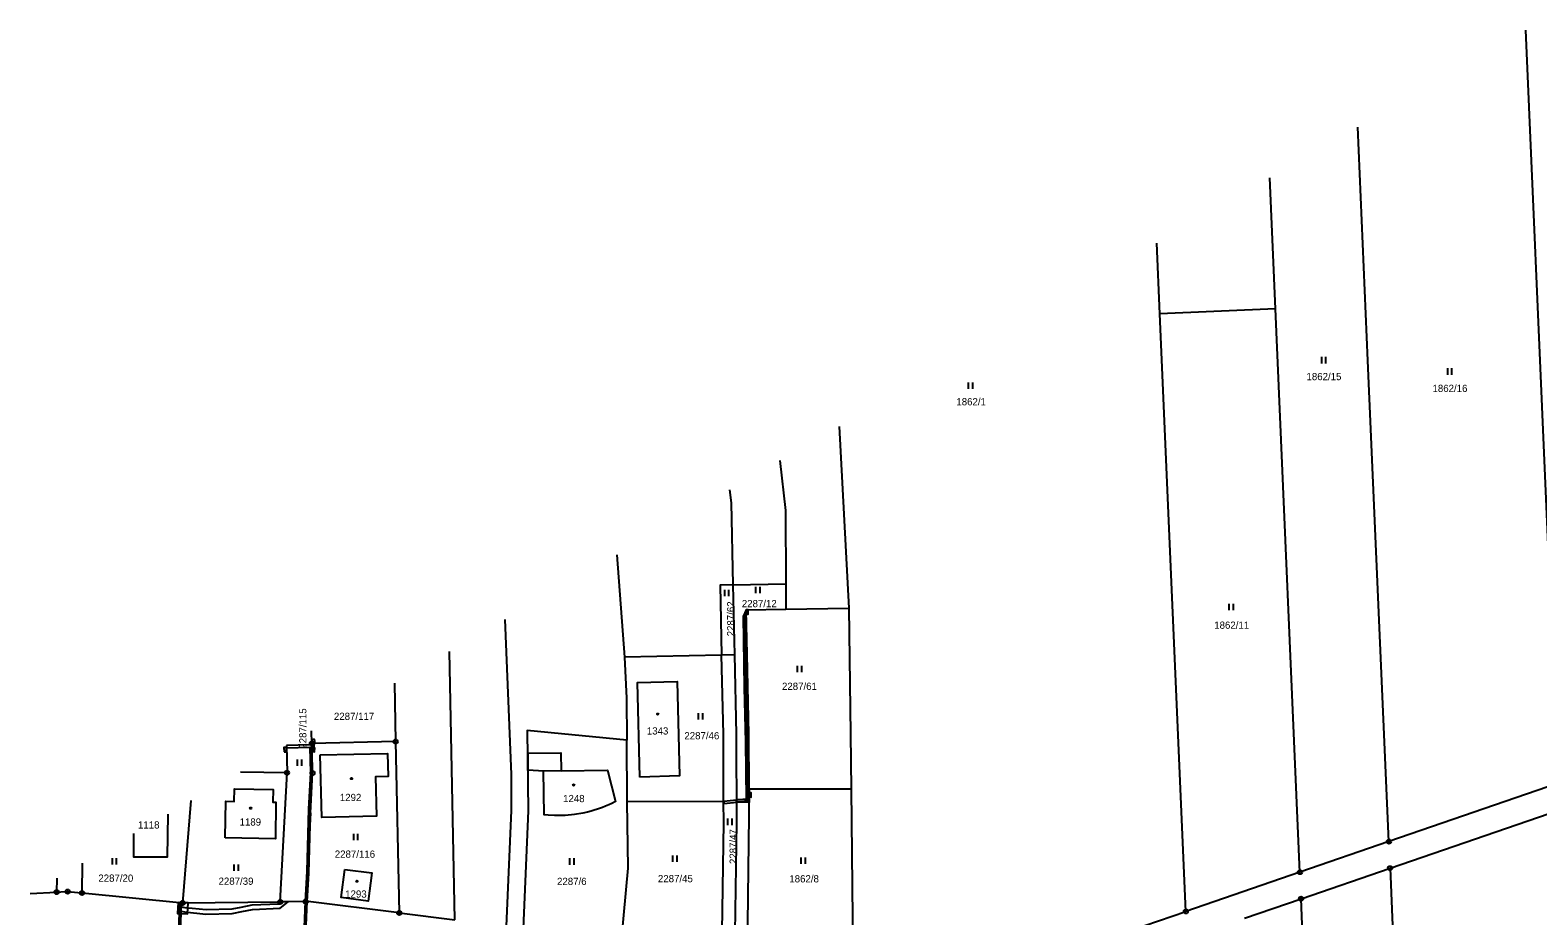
# Model space of a CAD drawing. Extents: x -758836 to -757729, y -1175316 to -1174366.
# Drawn here: x -758454.6 to -758099.9, y -1174637.3 to -1174428.8 of the extents above; entities that cross this region are included whole.
import ezdxf

# ---------------------------------------------------------------- set-up
doc = ezdxf.new("R2010")
doc.units = 0
for name, color, linetype in [('Hranice parcel', 7, 'Continuous'), ('Parcelní čísla', 7, 'Continuous'), ('Vnitřní kresba', 7, 'Continuous'), ('Věcná břemena k části', 7, 'Continuous'), ('Značky bodu BP', 7, 'Continuous'), ('Značky budov', 7, 'Continuous'), ('Značky kultur', 7, 'Continuous')]:
    doc.layers.add(name, color=color, linetype=linetype)

msp = doc.modelspace()

# ---------------------------------------------------------------- linework, layer by layer
at = {"layer": 'Hranice parcel'}
for p, q in [((-758094.97, -1174606.08), (-758102.68, -1174428.83)), ((-758161.61, -1174494.42), (-758162.95, -1174463.62)), ((-758188.8, -1174495.6), (-758189.52, -1174478.96)), ((-758161.61, -1174494.42), (-758188.8, -1174495.6)), ((-758182.68, -1174636.24), (-758188.8, -1174495.6)), ((-758155.84, -1174627.01), (-758161.61, -1174494.42)), ((-758289.28, -1174559.36), (-758276.79, -1174559.13)), ((-758289.28, -1174559.36), (-758288.91, -1174575.86)), ((-758276.79, -1174559.13), (-758276.77, -1174565.13)), ((-758276.77, -1174565.13), (-758261.99, -1174564.85)), ((-758354.67, -1174638.23), (-758355.96, -1174575.06)), ((-758291.91, -1174575.93), (-758314.73, -1174576.43)), ((-758288.91, -1174575.86), (-758291.91, -1174575.93)), ((-758368.92, -1174582.54), (-758368.63, -1174596.27)), ((-758388.32, -1174596.69), (-758388.38, -1174593.77)), ((-758394.31, -1174597.2), (-758394.18, -1174603.61)), ((-758368.63, -1174596.27), (-758388.32, -1174596.69)), ((-758368.63, -1174596.27), (-758367.77, -1174636.6)), ((-758314.16, -1174610.46), (-758314.25, -1174595.96)), ((-758394.18, -1174603.61), (-758405.13, -1174603.44)), ((-758395.77, -1174634), (-758394.18, -1174603.61)), ((-758094.97, -1174606.08), (-758134.89, -1174619.81)), ((-758285.46, -1174607.47), (-758285.9, -1174646.82)), ((-758261.42, -1174607.5), (-758285.46, -1174607.47)), ((-758261.42, -1174607.5), (-758261.03, -1174649.91)), ((-758291.45, -1174610.38), (-758314.16, -1174610.46)), ((-758134.62, -1174626.06), (-758094.69, -1174612.33)), ((-758134.89, -1174619.81), (-758155.84, -1174627.01)), ((-758155.84, -1174627.01), (-758182.68, -1174636.24)), ((-758155.57, -1174633.26), (-758134.62, -1174626.06)), ((-758134.62, -1174626.06), (-758130.45, -1174721.94)), ((-758454.62, -1174632.02), (-758448.39, -1174631.7)), ((-758442.4, -1174631.91), (-758418.72, -1174634.25)), ((-758418.72, -1174634.25), (-758395.77, -1174634)), ((-758389.77, -1174633.94), (-758395.77, -1174634)), ((-758168.89, -1174637.84), (-758155.57, -1174633.26)), ((-758152.07, -1174713.65), (-758155.57, -1174633.26)), ((-758367.77, -1174636.6), (-758354.67, -1174638.23))]:
    msp.add_line(p, q, dxfattribs=at)
for points in [[(-758134.89, -1174619.81), (-758139.82, -1174506.61), (-758142.21, -1174451.65)], [(-758264.27, -1174522.12), (-758261.99, -1174564.85)], [(-758278.19, -1174530.15), (-758276.85, -1174541.87), (-758276.79, -1174559.13)], [(-758290.03, -1174536.99), (-758289.7, -1174540.09), (-758289.28, -1174559.36)], [(-758316.58, -1174552.32), (-758314.73, -1174576.43)], [(-758289.28, -1174559.36), (-758292.28, -1174559.42), (-758291.91, -1174575.93)], [(-758285.46, -1174607.47), (-758285.5, -1174594.52), (-758285.91, -1174575.8), (-758286.14, -1174565.3), (-758276.77, -1174565.13)], [(-758261.99, -1174564.85), (-758261.59, -1174594.45), (-758261.42, -1174607.5)], [(-758342.95, -1174567.54), (-758341.45, -1174604.05), (-758341.43, -1174612.48), (-758342.58, -1174639.74)], [(-758314.73, -1174576.43), (-758314.27, -1174586.03), (-758314.25, -1174595.96)], [(-758291.45, -1174610.38), (-758291.5, -1174594.54), (-758291.91, -1174575.93)], [(-758288.91, -1174575.86), (-758288.5, -1174594.53), (-758288.43, -1174615.42), (-758288.89, -1174646.43)], [(-758311.15, -1174604.65), (-758311.72, -1174582.4), (-758302.38, -1174582.14), (-758301.8, -1174604.34), (-758311.15, -1174604.65)], [(-758314.25, -1174595.96), (-758337.67, -1174593.66), (-758337.43, -1174612.55), (-758338.6, -1174640.24)], [(-758389.77, -1174633.94), (-758388.18, -1174603.69), (-758388.32, -1174596.69)], [(-758386.35, -1174599.43), (-758370.51, -1174599.04), (-758370.38, -1174604.52), (-758373.34, -1174604.59), (-758373.1, -1174613.85), (-758386, -1174614.14), (-758386.35, -1174599.43)], [(-758332.74, -1174613.6), (-758333.68, -1174613.49), (-758333.82, -1174603.23), (-758337.4, -1174602.99), (-758337.47, -1174599), (-758329.76, -1174598.95), (-758329.68, -1174603.16), (-758318.75, -1174602.97), (-758316.89, -1174610.41), (-758317.73, -1174610.82), (-758318.48, -1174611.19), (-758319.21, -1174611.48), (-758319.98, -1174611.79), (-758321.1, -1174612.16), (-758321.88, -1174612.42), (-758322.64, -1174612.64), (-758323.44, -1174612.86), (-758324.57, -1174613.1), (-758326.53, -1174613.43), (-758328.71, -1174613.64), (-758330.15, -1174613.69), (-758331.27, -1174613.67), (-758332.74, -1174613.6)], [(-758408.71, -1174618.95), (-758408.59, -1174610.32), (-758406.58, -1174610.34), (-758406.55, -1174607.42), (-758397.43, -1174607.55), (-758397.52, -1174610.51), (-758396.8, -1174610.52), (-758396.9, -1174619.14), (-758408.71, -1174618.95)], [(-758418.72, -1174634.25), (-758416.76, -1174610.16)], [(-758315.47, -1174643.12), (-758313.89, -1174626.1), (-758314.16, -1174610.46)], [(-758291.89, -1174646.05), (-758291.43, -1174615.38), (-758291.45, -1174610.38)], [(-758422.24, -1174613.32), (-758422.37, -1174623.5), (-758430.22, -1174623.48), (-758430.2, -1174617.92)], [(-758442.4, -1174631.91), (-758442.32, -1174624.91)], [(-758380.61, -1174626.36), (-758374.22, -1174627.16), (-758375.09, -1174633.8), (-758381.45, -1174632.98), (-758380.61, -1174626.36)], [(-758448.35, -1174628.4), (-758448.39, -1174631.7)], [(-758448.39, -1174631.7), (-758447.39, -1174631.65), (-758445.79, -1174631.57), (-758443.39, -1174631.81), (-758442.4, -1174631.91)], [(-758367.77, -1174636.6), (-758389.23, -1174633.93), (-758389.77, -1174633.94)], [(-758212.86, -1174648.07), (-758198.75, -1174641.76), (-758182.68, -1174636.24)]]:
    msp.add_lwpolyline(points, dxfattribs=at)
at = {"layer": 'Vnitřní kresba'}
msp.add_line((-758329.68, -1174603.16), (-758333.82, -1174603.23), dxfattribs=at)
at = {"layer": 'Věcná břemena k části'}
for points in [[(-758286.12, -1174566.3), (-758286.14, -1174565.3), (-758286.82, -1174566.82), (-758286.63, -1174583.55), (-758286.32, -1174596.43), (-758286.12, -1174609.85), (-758288.45, -1174610.07), (-758288.45, -1174610.57), (-758285.62, -1174610.31), (-758285.82, -1174596.43), (-758286.13, -1174583.55), (-758286.32, -1174566.9)], [(-758285.69, -1174565.29), (-758286.14, -1174565.3), (-758286.12, -1174566.3), (-758285.67, -1174566.29)], [(-758394.85, -1174598.69), (-758394.28, -1174598.65), (-758394.31, -1174597.65), (-758394.91, -1174597.69)], [(-758394.31, -1174597.23), (-758394.3, -1174597.73), (-758388.8, -1174597.57), (-758388.68, -1174603.66), (-758389.13, -1174612.21), (-758389.5, -1174626.75), (-758389.93, -1174633.94), (-758389.77, -1174633.94), (-758388.67, -1174613.08), (-758388.18, -1174603.69), (-758388.28, -1174598.52), (-758388.31, -1174597.22), (-758388.8, -1174597.07)], [(-758387.69, -1174595.74), (-758388.34, -1174595.84), (-758388.32, -1174596.69), (-758387.55, -1174596.67)], [(-758387.54, -1174596.73), (-758387.55, -1174596.67), (-758388.32, -1174596.69), (-758388.32, -1174596.85)], [(-758388.31, -1174597.22), (-758388.28, -1174598.52), (-758388.1, -1174598.02), (-758387.8, -1174598.01), (-758387.82, -1174597.01), (-758388.31, -1174597.02)], [(-758387.65, -1174597.68), (-758388.3, -1174597.62), (-758388.28, -1174598.62), (-758387.74, -1174598.67)], [(-758285.97, -1174608.62), (-758285.95, -1174609.96), (-758288.45, -1174609.95), (-758288.45, -1174610.45), (-758285.49, -1174610.46), (-758285.48, -1174609.31), (-758285.47, -1174608.56)], [(-758285.47, -1174608.56), (-758285.48, -1174609.31), (-758284.98, -1174609.32), (-758284.97, -1174608.32), (-758285.47, -1174608.31)], [(-758388.67, -1174613.08), (-758389.77, -1174633.94), (-758389.42, -1174633.93), (-758389.03, -1174627.26)], [(-758288.45, -1174610.57), (-758288.45, -1174610.07), (-758291.36, -1174610.34), (-758291.32, -1174610.84)], [(-758417.46, -1174634.24), (-758418.72, -1174634.25), (-758419.79, -1174634.14), (-758419.91, -1174636.72), (-758417.57, -1174636.83)], [(-758419.22, -1174635.16), (-758419.42, -1174636.14), (-758418.28, -1174636.37), (-758413.27, -1174636.9), (-758407.06, -1174636.73), (-758404.82, -1174636.27), (-758402.33, -1174635.79), (-758395.76, -1174635.48), (-758393.88, -1174633.98), (-758395.51, -1174634), (-758396.14, -1174634.5), (-758402.45, -1174634.79), (-758405.02, -1174635.29), (-758407.18, -1174635.73), (-758413.23, -1174635.9), (-758418.12, -1174635.39)], [(-758389.42, -1174633.93), (-758389.77, -1174633.94), (-758389.93, -1174633.94), (-758390.26, -1174641.96), (-758389.02, -1174641.93), (-758387.42, -1174642.14), (-758387.35, -1174641.64), (-758388.96, -1174641.43), (-758389.74, -1174641.45)]]:
    msp.add_lwpolyline(points, close=True, dxfattribs=at)
msp.add_lwpolyline([(-758419.21, -1174641.86), (-758419.09, -1174636.24), (-758419.03, -1174634.95), (-758419.07, -1174634.22), (-758419.56, -1174634.17), (-758419.53, -1174634.93), (-758419.59, -1174636.22), (-758419.71, -1174641.86)], dxfattribs=at)
at = {"layer": 'Značky bodu BP'}
for centre, radius in [((-758388.32, -1174596.69), 0.5), ((-758388.32, -1174596.69), 0.0303), ((-758368.63, -1174596.27), 0.5), ((-758368.63, -1174596.27), 0.0303), ((-758394.18, -1174603.61), 0.5), ((-758394.18, -1174603.61), 0.0303), ((-758388.18, -1174603.69), 0.5), ((-758388.18, -1174603.69), 0.0303), ((-758134.89, -1174619.81), 0.5), ((-758134.89, -1174619.81), 0.0303), ((-758155.84, -1174627.01), 0.5), ((-758155.84, -1174627.01), 0.0303), ((-758134.62, -1174626.06), 0.5), ((-758134.62, -1174626.06), 0.0303), ((-758448.39, -1174631.7), 0.5), ((-758448.39, -1174631.7), 0.0303), ((-758445.79, -1174631.57), 0.5), ((-758445.79, -1174631.57), 0.0303), ((-758442.4, -1174631.91), 0.5), ((-758442.4, -1174631.91), 0.0303), ((-758418.72, -1174634.25), 0.5), ((-758418.72, -1174634.25), 0.0303), ((-758395.77, -1174634), 0.5), ((-758395.77, -1174634), 0.0303), ((-758389.77, -1174633.94), 0.5), ((-758389.77, -1174633.94), 0.0303), ((-758155.57, -1174633.26), 0.5), ((-758155.57, -1174633.26), 0.0303), ((-758367.77, -1174636.6), 0.5), ((-758367.77, -1174636.6), 0.0303), ((-758182.68, -1174636.24), 0.5), ((-758182.68, -1174636.24), 0.0303)]:
    msp.add_circle(centre, radius, dxfattribs=at)
at = {"layer": 'Značky budov'}
for centre in [(-758306.93, -1174589.81), (-758379, -1174604.98), (-758326.72, -1174606.5), (-758402.73, -1174611.95), (-758377.74, -1174629.14)]:
    msp.add_circle(centre, 0.175, dxfattribs=at)
at = {"layer": 'Značky kultur'}
for p, q in [((-758150.72, -1174507.25), (-758150.72, -1174505.75)), ((-758149.72, -1174507.25), (-758149.72, -1174505.75)), ((-758121.07, -1174509.92), (-758121.07, -1174508.42)), ((-758120.07, -1174509.92), (-758120.07, -1174508.42)), ((-758233.84, -1174513.25), (-758233.84, -1174511.75)), ((-758232.84, -1174513.25), (-758232.84, -1174511.75)), ((-758283.85, -1174561.38), (-758283.85, -1174559.88)), ((-758282.85, -1174561.38), (-758282.85, -1174559.88)), ((-758291.19, -1174562.04), (-758291.19, -1174560.54)), ((-758290.19, -1174562.04), (-758290.19, -1174560.54)), ((-758172.45, -1174565.38), (-758172.45, -1174563.88)), ((-758171.45, -1174565.38), (-758171.45, -1174563.88)), ((-758274.04, -1174579.94), (-758274.04, -1174578.44)), ((-758273.04, -1174579.94), (-758273.04, -1174578.44)), ((-758297.35, -1174591.1), (-758297.35, -1174589.6)), ((-758296.35, -1174591.1), (-758296.35, -1174589.6)), ((-758391.71, -1174601.98), (-758391.71, -1174600.48)), ((-758390.71, -1174601.98), (-758390.71, -1174600.48)), ((-758290.42, -1174615.91), (-758290.42, -1174614.41)), ((-758289.42, -1174615.91), (-758289.42, -1174614.41)), ((-758378.49, -1174619.49), (-758378.49, -1174617.99)), ((-758377.49, -1174619.49), (-758377.49, -1174617.99)), ((-758435.27, -1174625.2), (-758435.27, -1174623.7)), ((-758434.27, -1174625.2), (-758434.27, -1174623.7)), ((-758327.63, -1174625.25), (-758327.63, -1174623.75)), ((-758326.63, -1174625.25), (-758326.63, -1174623.75)), ((-758303.36, -1174624.61), (-758303.36, -1174623.11)), ((-758302.36, -1174624.61), (-758302.36, -1174623.11)), ((-758273.18, -1174625.05), (-758273.18, -1174623.55)), ((-758272.18, -1174625.05), (-758272.18, -1174623.55)), ((-758406.62, -1174626.67), (-758406.62, -1174625.17)), ((-758405.62, -1174626.67), (-758405.62, -1174625.17))]:
    msp.add_line(p, q, dxfattribs=at)

# ---------------------------------------------------------------- texts
at = {"layer": 'Parcelní čísla'}
for s, p in [('1862/15', (-758154.29, -1174511.21)), ('1862/16', (-758124.64, -1174513.99)), ('1862/1', (-758236.68, -1174517.13)), ('2287/12', (-758287.16, -1174564.64)), ('1862/11', (-758176, -1174569.72)), ('2287/61', (-758277.71, -1174584.11)), ('2287/117', (-758383.14, -1174591.18)), ('1343', (-758309.51, -1174594.61)), ('2287/46', (-758300.68, -1174595.74)), ('1292', (-758381.75, -1174610.27)), ('1248', (-758329.22, -1174610.53)), ('1118', (-758429.24, -1174616.73)), ('1189', (-758405.34, -1174616.05)), ('2287/116', (-758382.94, -1174623.61)), ('2287/20', (-758438.57, -1174629.26)), ('2287/39', (-758410.29, -1174629.98)), ('2287/6', (-758330.64, -1174630.03)), ('2287/45', (-758306.9, -1174629.38)), ('1862/8', (-758275.98, -1174629.42)), ('1293', (-758380.49, -1174633.01))]:
    msp.add_text(s, height=1.7, dxfattribs=at).set_placement(p)
for s, p in [('2287/62', (-758288.92, -1174571.5)), ('2287/115', (-758389.61, -1174597.94)), ('2287/47', (-758288.35, -1174625.1))]:
    msp.add_text(s, height=1.7, rotation=90, dxfattribs=at).set_placement(p)

doc.saveas('drawing.dxf')
